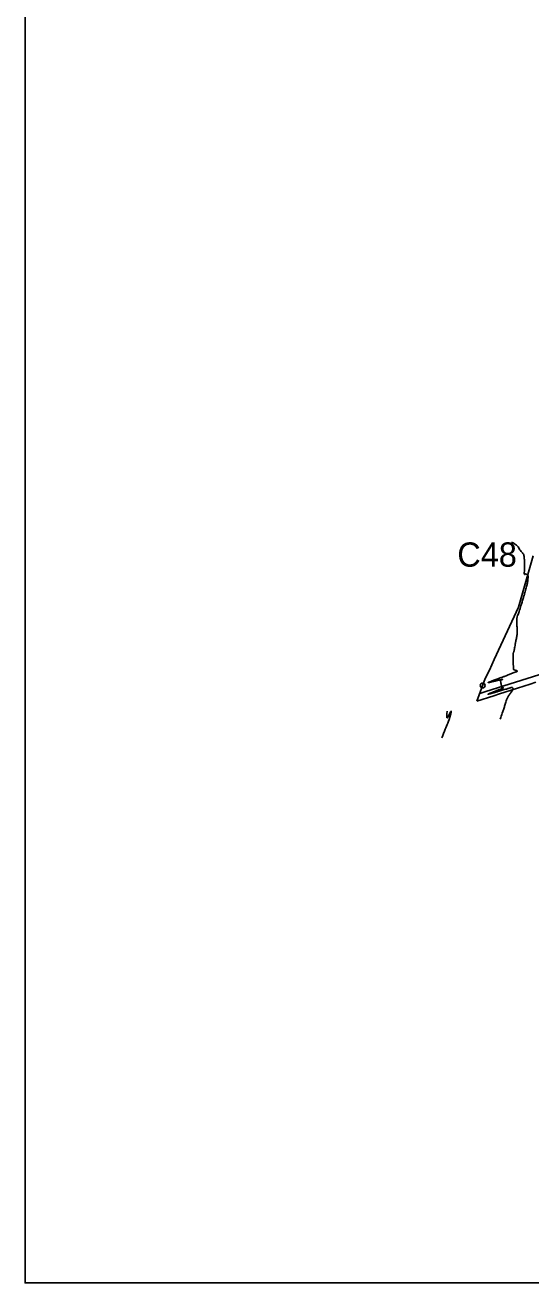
# Model space of a CAD drawing. Extents: x -478495 to -472450, y -1118050 to -1113745.
# Drawn here: x -478445 to -478028, y -1118000 to -1116963 of the extents above; entities that cross this region are included whole.
import ezdxf

# ---------------------------------------------------------------- set-up
doc = ezdxf.new("R2010")
doc.units = 0
for name, color, linetype in [('cesty', 7, 'Continuous'), ('hranice kú', 7, 'Continuous'), ('Implicitní', 7, 'Continuous'), ('ObPÚ', 7, 'Continuous'), ('silnice', 7, 'Continuous'), ('Vrstevnice_vedlejsi', 7, 'Continuous')]:
    doc.layers.add(name, color=color, linetype=linetype)

msp = doc.modelspace()

# ---------------------------------------------------------------- linework, layer by layer
at = {"layer": 'cesty'}
msp.add_circle((-478068.0933633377, -1117507.5012680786), 2, dxfattribs=at)
at = {"layer": 'hranice kú'}
for p, q in [((-478026.3550028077, -1117400.720715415), (-478038.5568606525, -1117443.0321937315)), ((-478038.5568606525, -1117443.0321937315), (-478058.48363570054, -1117486.0459372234)), ((-478058.48363570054, -1117486.0459372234), (-478062.43387743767, -1117494.999818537)), ((-478062.43387743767, -1117494.999818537), (-478065.94520343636, -1117501.846904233)), ((-478065.94520343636, -1117501.846904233), (-478072.8450766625, -1117520.4466069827)), ((-478049.81934647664, -1117513.067873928), (-478028.8541990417, -1117506.349466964)), ((-478028.8541990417, -1117506.349466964), (-478024.3605042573, -1117504.9094355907)), ((-478072.8450766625, -1117520.4466069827), (-478058.8128868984, -1117515.949907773)), ((-478058.8128868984, -1117515.949907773), (-478054.3161166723, -1117514.5088908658)), ((-478054.3161166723, -1117514.5088908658), (-478049.81934647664, -1117513.067873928))]:
    msp.add_line(p, q, dxfattribs=at)
at = {"layer": 'Implicitní'}
msp.add_lwpolyline([(-472500.12546831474, -1113795.0544653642), (-472500.125917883, -1118000.0544653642), (-478445.125917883, -1118000.053829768), (-478445.12546831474, -1113795.053829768)], close=True, dxfattribs=at)
at = {"layer": 'ObPÚ'}
for p, q in [((-478026.3550028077, -1117400.720715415), (-478038.5568606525, -1117443.0321937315)), ((-478038.5568606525, -1117443.0321937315), (-478058.48363570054, -1117486.0459372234)), ((-478058.48363570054, -1117486.0459372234), (-478062.43387743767, -1117494.999818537)), ((-478062.43387743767, -1117494.999818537), (-478065.94520343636, -1117501.846904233)), ((-478065.94520343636, -1117501.846904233), (-478072.8450766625, -1117520.4466069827)), ((-478049.81934647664, -1117513.067873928), (-478028.8541990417, -1117506.349466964)), ((-478028.8541990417, -1117506.349466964), (-478024.3605042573, -1117504.9094355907)), ((-478072.8450766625, -1117520.4466069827), (-478058.8128868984, -1117515.949907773)), ((-478058.8128868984, -1117515.949907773), (-478054.3161166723, -1117514.5088908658)), ((-478054.3161166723, -1117514.5088908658), (-478049.81934647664, -1117513.067873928))]:
    msp.add_line(p, q, dxfattribs=at)
at = {"layer": 'silnice'}
msp.add_lwpolyline([(-478070.49536841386, -1117514.1125956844), (-478065.5203558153, -1117512.4650769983), (-477835.70100830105, -1117440.2943423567), (-477736.72771266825, -1117410.083337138), (-477702.33868620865, -1117405.048169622), (-477652.85203839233, -1117401.6913912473), (-477590.7840394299, -1117403.36978045), (-477332.44696264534, -1117414.2793100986), (-477204.95593777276, -1117416.7968938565), (-477142.0491820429, -1117416.7968938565), (-477096.7563179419, -1117410.083337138), (-477037.20458922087, -1117399.1738074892), (-476978.49161720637, -1117379.0331373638), (-476883.71210528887, -1117344.6261592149), (-476756.22108038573, -1117298.470456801), (-476633.76259959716, -1117254.8324505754), (-476588.4697354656, -1117242.244531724), (-476550.72568205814, -1117234.6917804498), (-476503.7553044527, -1117230.4958074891), (-476424.07341389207, -1117228.8174183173)], dxfattribs=at)
at = {"layer": 'Vrstevnice_vedlejsi'}
msp.add_line((-478053.213, -1117534.03), (-478053.6870084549, -1117535.3091993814), dxfattribs=at)
for points in [[(-478044.3227972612, -1117389.4969368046), (-478042.996, -1117389.964), (-478040.645, -1117391.528), (-478038.938, -1117393.1570000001), (-478037.876, -1117394.852), (-478036.855, -1117396.325), (-478035.874, -1117397.575), (-478034.935, -1117398.602), (-478034.275, -1117399.76), (-478033.895, -1117401.05), (-478033.795, -1117402.47), (-478033.734, -1117403.5590000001), (-478033.712, -1117404.316), (-478033.729, -1117404.741), (-478033.72500000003, -1117405.5960000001), (-478033.699, -1117406.882), (-478033.652, -1117408.598), (-478033.647, -1117410.423), (-478033.685, -1117412.357), (-478033.765, -1117414.398), (-478033.662, -1117415.636), (-478033.37700000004, -1117416.07), (-478032.909, -1117415.7), (-478032.433, -1117415.597), (-478031.94800000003, -1117415.763), (-478031.455, -1117416.196), (-478031.09500000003, -1117416.556), (-478030.869, -1117416.842), (-478030.778, -1117417.054), (-478030.702, -1117417.25), (-478030.642, -1117417.43), (-478030.599, -1117417.594), (-478030.63300000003, -1117418.2650000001), (-478030.746, -1117419.442), (-478030.936, -1117421.127), (-478031.189, -1117422.771), (-478031.506, -1117424.376), (-478031.885, -1117425.94), (-478032.413, -1117427.911), (-478033.08900000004, -1117430.288), (-478033.913, -1117433.072), (-478034.768, -1117435.929), (-478035.655, -1117438.861), (-478036.572, -1117441.865), (-478037.25800000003, -1117444.074), (-478037.711, -1117445.486), (-478037.933, -1117446.102), (-478038.32300000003, -1117447.233), (-478038.882, -1117448.881), (-478039.609, -1117451.044), (-478039.974, -1117453.668), (-478039.978, -1117456.752), (-478039.62, -1117460.297), (-478039.614, -1117463.766), (-478039.96, -1117467.16), (-478040.659, -1117470.4780000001), (-478041.215, -1117473.3090000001), (-478041.62700000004, -1117475.65), (-478041.895, -1117477.504), (-478042.188, -1117478.963), (-478042.50800000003, -1117480.028), (-478042.852, -1117480.698), (-478043.034, -1117482.402), (-478043.052, -1117485.1400000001), (-478042.907, -1117488.911), (-478042.811, -1117491.6230000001), (-478042.76300000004, -1117493.276), (-478042.764, -1117493.87), (-478042.605, -1117494.312), (-478042.286, -1117494.604), (-478041.80700000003, -1117494.745), (-478041.205, -1117494.94), (-478040.478, -1117495.19), (-478039.628, -1117495.494), (-478039.61, -1117495.8800000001), (-478040.424, -1117496.348), (-478042.07, -1117496.896), (-478043.579, -1117497.431), (-478044.951, -1117497.952), (-478046.18700000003, -1117498.458), (-478047.753, -1117499.08), (-478049.64900000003, -1117499.817), (-478051.876, -1117500.669), (-478053.635, -1117501.33), (-478054.925, -1117501.799), (-478055.746, -1117502.077), (-478056.417, -1117502.312), (-478056.936, -1117502.5050000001), (-478057.304, -1117502.655), (-478058.15, -1117502.98), (-478059.473, -1117503.48)], [(-478059.473, -1117503.48), (-478061.273, -1117504.155), (-478062.505, -1117504.62), (-478063.169, -1117504.874), (-478063.265, -1117504.919), (-478063.348, -1117504.9510000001), (-478063.419, -1117504.972), (-478063.477, -1117504.981), (-478063.52400000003, -1117504.995), (-478063.56, -1117505.013), (-478063.585, -1117505.036), (-478063.59500000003, -1117505.066), (-478063.591, -1117505.1030000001), (-478063.57, -1117505.147), (-478063.526, -1117505.177), (-478063.458, -1117505.1940000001), (-478063.36600000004, -1117505.198), (-478063.254, -1117505.189), (-478063.124, -1117505.1670000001), (-478062.974, -1117505.132), (-478062.359, -1117504.9780000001), (-478061.278, -1117504.705), (-478059.732, -1117504.311), (-478058.385, -1117503.975), (-478057.239, -1117503.697), (-478056.293, -1117503.477), (-478055.194, -1117503.2010000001), (-478053.942, -1117502.871), (-478052.538, -1117502.485), (-478051.841, -1117502.369), (-478051.851, -1117502.521), (-478052.569, -1117502.943), (-478053.063, -1117503.23), (-478053.33400000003, -1117503.384), (-478053.381, -1117503.404), (-478053.347, -1117503.774), (-478053.23, -1117504.495), (-478053.03, -1117505.565), (-478052.853, -1117506.552), (-478052.69800000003, -1117507.454), (-478052.564, -1117508.272), (-478052.466, -1117508.842), (-478052.403, -1117509.165), (-478052.374, -1117509.239), (-478052.188, -1117509.294), (-478051.84500000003, -1117509.328), (-478051.344, -1117509.342), (-478051.064, -1117509.394), (-478051.005, -1117509.486), (-478051.168, -1117509.616), (-478051.427, -1117509.761), (-478051.782, -1117509.921), (-478052.234, -1117510.097), (-478052.683, -1117510.269), (-478053.128, -1117510.439), (-478053.57, -1117510.606), (-478054.428, -1117510.9340000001), (-478055.701, -1117511.423), (-478057.392, -1117512.072), (-478059.194, -1117512.787), (-478061.11, -1117513.568), (-478063.13800000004, -1117514.415), (-478063.798, -1117514.79), (-478063.08900000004, -1117514.692), (-478061.01, -1117514.1230000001), (-478059.39, -1117513.6670000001), (-478058.228, -1117513.324), (-478057.52400000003, -1117513.095), (-478056.651, -1117512.821), (-478055.61, -1117512.502), (-478054.401, -1117512.139), (-478052.94800000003, -1117511.707), (-478051.253, -1117511.208), (-478049.313, -1117510.6400000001), (-478047.84, -1117510.209), (-478046.831, -1117509.914), (-478046.288, -1117509.7550000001), (-478045.694, -1117509.584), (-478045.048, -1117509.401), (-478044.351, -1117509.205), (-478043.802, -1117509.2280000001), (-478043.401, -1117509.4710000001), (-478043.14900000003, -1117509.932), (-478042.982, -1117510.283), (-478042.902, -1117510.524), (-478042.908, -1117510.653), (-478043.44800000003, -1117511.466), (-478044.521, -1117512.962), (-478046.128, -1117515.142), (-478047.422, -1117517.235), (-478048.402, -1117519.244), (-478049.068, -1117521.166), (-478049.621, -1117522.911), (-478050.059, -1117524.479), (-478050.382, -1117525.869), (-478051.434, -1117529.052), (-478053.213, -1117534.03)], [(-478097.2604944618, -1117528.7594959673), (-478097.327, -1117534.259), (-478094.06200000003, -1117528.696), (-478094.59, -1117531.824), (-478098.909, -1117543.642), (-478101.70189623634, -1117550.6970949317)]]:
    msp.add_spline(points, degree=3, dxfattribs=at)

# ---------------------------------------------------------------- texts
at = {"layer": 'cesty'}
msp.add_text('C48', height=19.99999999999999, rotation=359.99999385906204, dxfattribs=at).set_placement((-478088.9667094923, -1117409.567745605))

doc.saveas('drawing.dxf')
